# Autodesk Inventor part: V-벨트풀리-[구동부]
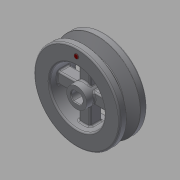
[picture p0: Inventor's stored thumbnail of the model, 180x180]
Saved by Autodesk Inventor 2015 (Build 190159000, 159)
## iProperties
Created: 2018-01
Part Number: V-벨트풀리-[구동부]
Material: 스테인리스강
Document SubType Name: Modeling
Designer: mduedu
Density: 8.08 g/cm^3
Mass: 218.724 g
Surface Area: 130.785 cm^2
Volume: 27.0698 cm^3
Appearance: 기본값
Author: mduedu
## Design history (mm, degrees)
sketch "스케치1"
  geometry: C1 r 30 at (0, 0); 1 further point
  constraints: 1 centre point, 1 coincident
  dimensions: "d0" = 60 diameter of C1
extrude "돌출1" new body sketch "스케치1" stored distance "d1" = 19; taper "d2" = 0 deg
sketch "스케치2"
  geometry: L1 (30, -9.5)-(-30, -9.5) reference; L2 (-30, -9.5)-(-30, 9.5) reference; L3 (-30, 9.5)-(30, 9.5) reference; L4 (30, 9.5)-(30, -9.5) reference; L5 (-30, 0)-(30, 0); L6 (30, 4.825)-(21, 2.074); L7 (21, 2.074)-(21, -2.074); L8 (21, -2.074)-(30, -4.825); L9 (30, -4.825)-(30, 4.825); L10 (27.3, 9.5)-(27.3, -9.5); L11 (0, -13.3)-(0, 13.3) reference; 4 further points
  constraints: 12 end point, 9 point on line, 3 midpoint, 2 perpendicular, 1 collinear, 1 symmetric about line
  dimensions: "d3" = 34 deg angle of L8 L6; "d4" = 2.7 distance between parallel lines of L10 L4; "d5" = 6.3 distance between parallel lines of L7 L10; "d6" = 8 distance of point (27.3, -4) point (27.3, 4)
revolve "회전1" sketch "스케치2" stored, may be unused: angle "d7" = 90 deg
fillet "모깎기1" dims "d8" = 0.2
fillet "모깎기2" dims "d9" = 0.5
fillet "모깎기3" dims "d10" = 1
sketch "스케치3"
  geometry: C1 r 19 at (0, 0); 1 further point
  constraints: 1 centre point, 1 coincident
  dimensions: "d11" = 38 diameter of C1
extrude "돌출2" cut sketch "스케치3" stored distance "d12" = 19; taper "d13" = 0 deg
sketch "스케치4"
  geometry: C1 r 7 at (0, 0); 1 further point
  constraints: 1 centre point, 1 coincident
  dimensions: "d14" = 14 diameter of C1
extrude "돌출3" join sketch "스케치4" stored distance "d15" = 19; taper "d16" = 0 deg
sketch "스케치5"
  geometry: L1 (0, 7)-(0, 19); L2 (4, 5.745)-(4, 18.574); L3 (-4, 5.745)-(-4, 18.574); C1 r 21 at (0, 0) reference; A1 r 19 centre (0, 0) between (0, 19) and (-4, 18.574) reference; A2 r 7 centre (0, 0) between (0, 7) and (-4, 5.745) reference; 1 further point
  constraints: 6 end point, 6 point on circle, 2 parallel, 1 point on line, 1 vertical, 1 other
  dimensions: "d17" = 8 distance between parallel lines of L2 L3
extrude "돌출4" join sketch "스케치5" stored distance "d18" = 8; taper "d19" = 0 deg
fillet "모깎기4" dims "d20" = 1
fillet "모깎기5" dims "d24" = 1
fillet "모깎기6" dims "d25" = 1
hole "구멍1" diameter "d28" = 8; stored, may be unused: countersink angle "d32" = 90 deg, drill point angle "d34" = 118 deg; dims "d26" = 10, "d27" = 10, "d29" = 6, "d30" = 4, "d31" = 2, "d33" = 8
sketch "스케치6"
  geometry: L1 (-2.332, -3.25)-(2.332, -3.25); L2 (2.332, 3.25)-(-2.332, 3.25); L3 (-2.332, -3.25)-(2.332, 3.25); L4 (2.332, -3.25)-(-2.332, 3.25); A1 r 4 centre (0, 0) between (2.332, 3.25) and (-2.332, 3.25) reference; A2 r 4 centre (0, 0) between (2.332, 3.25) and (-2.332, 3.25); A3 r 4 centre (0, 0) between (-2.332, -3.25) and (2.332, -3.25); 1 further point
  constraints: 8 end point, 7 point on circle, 2 centre point, 2 coincident, 2 midpoint, 1 horizontal, 1 parallel
  dimensions: "d35" = 6.5 distance of L1.end L2.start
extrude "돌출5" join sketch "스케치6" stored distance "d37" = 8; taper "d38" = 0 deg
chamfer "모따기1" distance "d39" = 0.5; stored, may be unused: second distance "d40" = 2, angle "d41" = 45 deg
chamfer "모따기2" distance "d42" = 0.5; stored, may be unused: second distance "d43" = 2, angle "d44" = 45 deg
sketch "스케치7" dims "d45" = 50
  geometry: C1 r 1.5 at (0, 25); 2 further points
  constraints: 2 vertical alignment, 1 centre point, 1 coincident, 2 other
  dimensions: "d46" = 3 diameter of C1
extrude "돌출6" join sketch "스케치7" distance "d47" = 0.5; taper "d48" = 0 deg
fillet "모깎기7" dims "d49" = 0.1
node "솔리드1"
pattern_circular "원형 패턴1" dims angle "d22" = 360 deg
node "절단 모서리 투영1"
node "절단 모서리 투영2"
